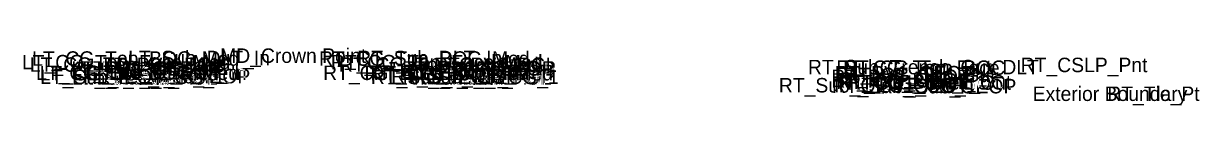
# Model space of a CAD drawing. Extents: x -26 to 6300, y -10 to 9528.
# Drawn here: x 2126 to 2207.4, y 5017.8 to 5021.8 of the extents above; entities that cross this region are included whole.
import ezdxf

# ---------------------------------------------------------------- set-up
doc = ezdxf.new("R2010")
doc.units = 0
doc.layers.add('Default', color=7, linetype='Continuous')

msp = doc.modelspace()

# ---------------------------------------------------------------- texts
at = {"layer": 'Default'}
for s, p in [('LT_CG_Top_Face_Med', (2125.866, 5020.258)), ('LT_CG_Top_Gut_Med', (2126.418, 5020.091)), ('LT_CG_Top_BOC_Med', (2126.569, 5020.508)), ('LT_PV1_PGL', (2131.503, 5020.076)), ('LT_Sub_DLT_In', (2133.217, 5020.548)), ('MD_Crown Point', (2139.582, 5020.708)), ('RT_CG_Top_BOC_Med', (2146.431, 5020.508)), ('RT_CG_Top_Face_Med', (2147.246, 5020.258)), ('RT_CG_Top_Gut_Med', (2147.8, 5020.091)), ('RT_Sub_DLT_In', (2149.068, 5020.548)), ('RT_PV1_PGL', (2154.385, 5020.076)), ('RT_Sub_Trench_Out_DLT', (2180.257, 5019.918)), ('RT_CSLP_Pnt', (2194.982, 5020.066)), ('LT_CG_Bot_BOC_Med', (2126.846, 5019.523)), ('LT_CG_Bot_IE_Med', (2127.094, 5019.493)), ('LT_Sub_IEOT_CG_1', (2127.125, 5019.243)), ('LT_PV2_OEEOP', (2129.285, 5019.826)), ('LT_PV3_OEEOP', (2129.285, 5019.576)), ('LT_Sub_OEEOP', (2129.332, 5019.201)), ('LT_PV2_IEEOP', (2130.046, 5019.826)), ('LT_Sub_IEEOP', (2130.093, 5019.201)), ('LT_CG1_Shelf_In', (2130.712, 5019.533)), ('LT_PV2_PGL', (2131.264, 5019.826)), ('LT_Sub_PGL', (2131.311, 5019.201)), ('LT_Sub_IEOP', (2133.045, 5019.288)), ('RT_CG_Bot_BOC_Med', (2146.708, 5019.523)), ('RT_CG1_Shelf_In', (2149.573, 5019.533)), ('RT_CG_Bot_IE_Med', (2149.976, 5019.493)), ('RT_Sub_IEOT_CG_1', (2150.007, 5019.243)), ('RT_Sub_IEOP', (2151.417, 5019.288)), ('RT_PV2_OEEOP', (2152.167, 5019.826)), ('RT_PV3_OEEOP', (2152.167, 5019.576)), ('RT_Sub_OEEOP', (2152.214, 5019.201)), ('RT_PV2_IEEOP', (2152.928, 5019.826)), ('RT_Sub_IEEOP', (2152.975, 5019.201)), ('RT_PV2_PGL', (2154.145, 5019.826)), ('RT_Sub_PGL', (2154.192, 5019.201)), ('RT_PV2_OEOT', (2181.873, 5019.246)), ('RT_PV1_OEOT', (2182.112, 5019.496)), ('RT_CG_Top_Face', (2182.225, 5019.876)), ('RT_CG_Top_BOC', (2182.694, 5019.876)), ('RT_CG_Top_Gut', (2182.752, 5019.376)), ('RT_Sub_OEOT_CG_1', (2178.247, 5018.663)), ('RT_PV3_OEOT', (2181.873, 5018.996)), ('RT_Sub_OEOT', (2181.92, 5018.621)), ('RT_CG_Bot_IE', (2182.221, 5018.913)), ('RT_CG1_Shelf_Out', (2182.36, 5018.853)), ('RT_CG_Bot_BOC', (2182.97, 5018.863)), ('RT_Sub_OEOP', (2185.166, 5018.598)), ('Exterior Boundary', (2195.809, 5018.073)), ('RT_Tie_Pt', (2200.972, 5018.073))]:
    msp.add_text(s, height=1, dxfattribs=at).set_placement(p)

doc.saveas('drawing.dxf')
